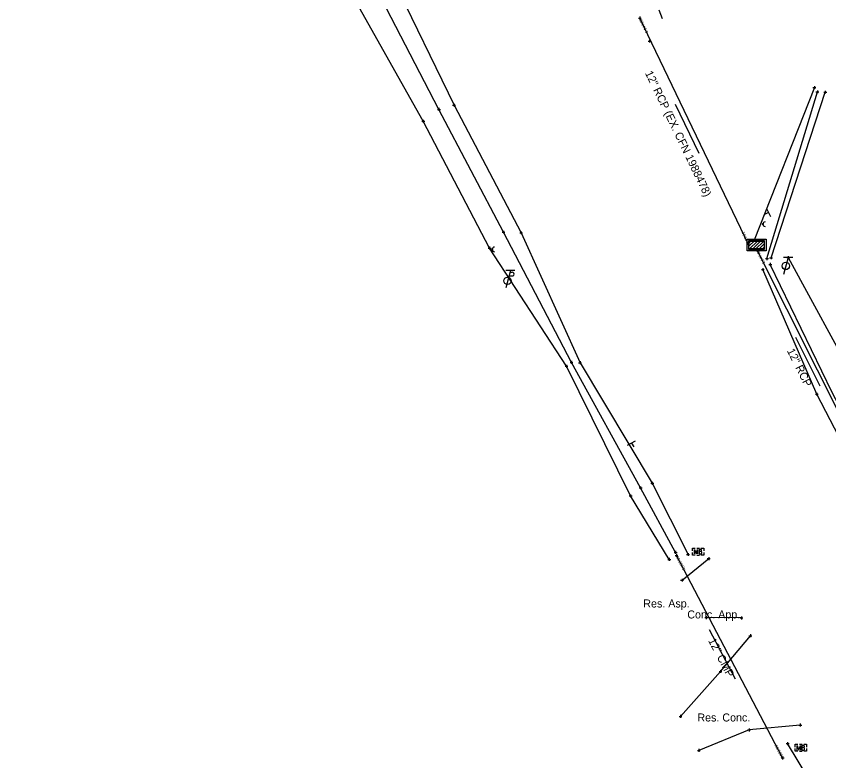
# Model space of a CAD drawing. Extents: x 2298098 to 2302860, y 557788 to 564251.
# Drawn here: x 2298773 to 2299057.3, y 562447.4 to 562708 of the extents above; entities that cross this region are included whole.
import ezdxf

# ---------------------------------------------------------------- set-up
doc = ezdxf.new("R2010")
doc.units = 0
for name, color, linetype in [('DR_X_Cells', 7, 'Continuous'), ('DR_X_Ditch', 7, 'Continuous'), ('DR_X_Elev_Flow', 7, 'Continuous'), ('DR_X_Storm_Sewer', 7, 'Continuous'), ('DR_X_Text', 7, 'Continuous'), ('GK_Drainage_Nodes', 7, 'Continuous'), ('PV_X_Driveway', 7, 'Continuous'), ('PV_X_Text', 7, 'Continuous'), ('RD_X_Cells', 7, 'Continuous'), ('SC_Scratch1', 7, 'Continuous'), ('SN_X_Public', 7, 'Continuous'), ('SV_X_Break_Lines', 7, 'Continuous'), ('SV_X_Shot_Marker', 7, 'Continuous'), ('UT_X_Misc_Cells', 7, 'Continuous'), ('UT_X_Telecom_Cells', 7, 'Continuous')]:
    doc.layers.add(name, color=color, linetype=linetype)

msp = doc.modelspace()

# ---------------------------------------------------------------- linework, layer by layer
at = {"layer": 'DR_X_Cells'}
for p, q in [((2299029.41, 562626.34), (2299032.59, 562629.53)), ((2299029.41, 562627.48), (2299031.46, 562629.53)), ((2299029.41, 562628.61), (2299030.33, 562629.53)), ((2299030.5, 562626.3), (2299033.72, 562629.53)), ((2299031.63, 562626.3), (2299034.74, 562629.41)), ((2299032.76, 562626.3), (2299034.74, 562628.28)), ((2299033.89, 562626.3), (2299034.74, 562627.15))]:
    msp.add_line(p, q, dxfattribs=at)
for points in [[(2299028.74, 562629.91), (2299035.41, 562629.91), (2299035.41, 562625.91), (2299028.74, 562625.91)], [(2299029.41, 562629.53), (2299034.74, 562629.53), (2299034.74, 562626.3), (2299029.41, 562626.3)], [(2299029.41, 562629.25), (2299034.74, 562629.25), (2299034.74, 562626.58), (2299029.41, 562626.58)]]:
    msp.add_lwpolyline(points, close=True, dxfattribs=at)
at = {"layer": 'DR_X_Ditch'}
for points in [[(2299003.75, 562520.37), (2298991.5, 562542.96), (2298967.32, 562586.85), (2298943.53, 562632.42), (2298920.95, 562675.39), (2298897.6, 562720.52), (2298875.32, 562763.99), (2298851.88, 562808.58), (2298829.06, 562850.95), (2298804.9, 562894.79), (2298774.65, 562954.26)], [(2299035.71, 562623.16), (2299053.35, 562681.54)], [(2299086.62, 562522.02), (2299079.1, 562537.23), (2299058.55, 562576.3), (2299036.88, 562621.13)]]:
    msp.add_lwpolyline(points, dxfattribs=at)
at = {"layer": 'DR_X_Elev_Flow'}
for p, q in [((2298990.71, 562707.35), (2298991.71, 562707.35)), ((2298991.21, 562707.85), (2298991.21, 562706.85)), ((2298991.21, 562707.35), (2298991.21, 562707.35)), ((2298994.1, 562699.27), (2298995.1, 562699.27)), ((2298994.6, 562699.77), (2298994.6, 562698.77)), ((2298994.6, 562699.27), (2298994.6, 562699.27)), ((2299003.56, 562519.29), (2299004.56, 562519.29)), ((2299004.06, 562519.79), (2299004.06, 562518.79)), ((2299004.06, 562519.29), (2299004.06, 562519.29)), ((2299040.69, 562448.42), (2299041.69, 562448.42)), ((2299041.19, 562448.92), (2299041.19, 562447.92)), ((2299041.19, 562448.42), (2299041.19, 562448.42))]:
    msp.add_line(p, q, dxfattribs=at)
at = {"layer": 'DR_X_Storm_Sewer'}
for p, q in [((2299029.41, 562627.91), (2298991.21, 562707.35)), ((2299101.62, 562487.9), (2299032.08, 562626.58)), ((2299041.19, 562448.42), (2299004.06, 562519.29))]:
    msp.add_line(p, q, dxfattribs=at)
at = {"layer": 'DR_X_Text'}
for p, q in [((2299003.59, 562677.21), (2299011.87, 562660.01)), ((2299045.71, 562595.69), (2299054.27, 562578.63)), ((2299015.48, 562493.39), (2299024.54, 562476.1))]:
    msp.add_line(p, q, dxfattribs=at)
at = {"layer": 'GK_Drainage_Nodes'}
for p, q in [((2299032.08, 562629.91), (2299032.08, 562629.91)), ((2299029.41, 562627.91), (2299029.41, 562627.91)), ((2299032.08, 562629.25), (2299032.08, 562629.25)), ((2299032.08, 562627.91), (2299032.08, 562627.91)), ((2299032.08, 562627.91), (2299032.08, 562627.91)), ((2299034.74, 562627.91), (2299034.74, 562627.91)), ((2299032.08, 562626.58), (2299032.08, 562626.58)), ((2299032.08, 562626.3), (2299032.08, 562626.3)), ((2299032.08, 562625.91), (2299032.08, 562625.91))]:
    msp.add_line(p, q, dxfattribs=at)
at = {"layer": 'PV_X_Driveway'}
for p, q in [((2299047.39, 562459.92), (2299029.46, 562458.23)), ((2299029.46, 562458.23), (2299011.87, 562451.06))]:
    msp.add_line(p, q, dxfattribs=at)
for points in [[(2299006, 562510.62), (2299015.35, 562518.16)], [(2299026.8, 562497.42), (2299014.48, 562497.53)], [(2299005.44, 562462.97), (2299019.44, 562478.67), (2299029.93, 562491.18)]]:
    msp.add_lwpolyline(points, dxfattribs=at)
at = {"layer": 'RD_X_Cells'}
for p, q in [((2299011.12, 562521.83), (2299012.12, 562521.83)), ((2299011.12, 562519.39), (2299012.12, 562519.39)), ((2299011.63, 562520.61), (2299011.63, 562520.61)), ((2299047.09, 562453.22), (2299048.09, 562453.22)), ((2299047.09, 562450.78), (2299048.09, 562450.78)), ((2299047.6, 562452), (2299047.6, 562452))]:
    msp.add_line(p, q, dxfattribs=at)
for points in [[(2299009.63, 562520.86), (2299009.63, 562521.83), (2299010.6, 562521.83)], [(2299012.63, 562521.83), (2299013.63, 562521.83), (2299013.63, 562520.86)], [(2299010.6, 562519.39), (2299009.63, 562519.39), (2299009.63, 562520.36)], [(2299010.33, 562519.81), (2299010.33, 562521.41), (2299010.91, 562519.81), (2299011.46, 562521.41), (2299011.46, 562519.81)], [(2299012.65, 562520.68), (2299012.71, 562520.74), (2299012.75, 562520.78), (2299012.77, 562520.82), (2299012.79, 562520.84), (2299012.81, 562520.89), (2299012.83, 562520.93), (2299012.85, 562521.02), (2299012.85, 562521.06), (2299012.85, 562521.11), (2299012.84, 562521.18), (2299012.81, 562521.24), (2299012.77, 562521.29), (2299012.71, 562521.34), (2299012.66, 562521.37), (2299012.64, 562521.38), (2299012.57, 562521.41), (2299011.96, 562521.41), (2299011.96, 562519.81), (2299012.65, 562519.81), (2299012.74, 562519.86), (2299012.81, 562519.92), (2299012.88, 562520.02), (2299012.91, 562520.14), (2299012.93, 562520.25), (2299012.93, 562520.32), (2299012.9, 562520.4), (2299012.85, 562520.51), (2299012.79, 562520.59), (2299012.65, 562520.68), (2299011.96, 562520.68)], [(2299013.63, 562520.36), (2299013.63, 562519.39), (2299012.63, 562519.39)], [(2299045.6, 562452.25), (2299045.6, 562453.22), (2299046.57, 562453.22)], [(2299046.57, 562450.78), (2299045.6, 562450.78), (2299045.6, 562451.75)], [(2299046.3, 562451.2), (2299046.3, 562452.8), (2299046.88, 562451.2), (2299047.44, 562452.8), (2299047.44, 562451.2)], [(2299048.62, 562452.07), (2299048.68, 562452.13), (2299048.72, 562452.17), (2299048.75, 562452.21), (2299048.76, 562452.23), (2299048.78, 562452.28), (2299048.8, 562452.32), (2299048.82, 562452.41), (2299048.82, 562452.45), (2299048.82, 562452.5), (2299048.81, 562452.57), (2299048.78, 562452.64), (2299048.75, 562452.69), (2299048.68, 562452.74), (2299048.63, 562452.76), (2299048.61, 562452.78), (2299048.55, 562452.8), (2299047.93, 562452.8), (2299047.93, 562451.2), (2299048.62, 562451.2), (2299048.71, 562451.25), (2299048.78, 562451.31), (2299048.85, 562451.42), (2299048.89, 562451.53), (2299048.9, 562451.64), (2299048.9, 562451.72), (2299048.87, 562451.79), (2299048.82, 562451.91), (2299048.76, 562451.98), (2299048.62, 562452.07), (2299047.93, 562452.07)], [(2299048.61, 562453.22), (2299049.6, 562453.22), (2299049.6, 562452.25)], [(2299049.6, 562451.75), (2299049.6, 562450.78), (2299048.61, 562450.78)]]:
    msp.add_lwpolyline(points, dxfattribs=at)
at = {"layer": 'SN_X_Public'}
for p, q in [((2298997.91, 562710.16), (2298999.07, 562707.18)), ((2299036.25, 562639.33), (2299034.83, 562638.59)), ((2299035.51, 562640.75), (2299036.99, 562637.91)), ((2298986.92, 562557.82), (2298989.69, 562559.44)), ((2298988.31, 562558.63), (2298989.11, 562557.25))]:
    msp.add_line(p, q, dxfattribs=at)
at = {"layer": 'SV_X_Break_Lines'}
for points in [[(2298776.72, 562954.86), (2298790.71, 562942.29), (2298813.67, 562899.02), (2298836.78, 562854.64), (2298857.48, 562808.76), (2298880.71, 562765.1), (2298904.94, 562720.81), (2298926.21, 562676.8), (2298949.69, 562632.19), (2298970.3, 562586.72), (2298995.59, 562544.53), (2299008.11, 562519.62)], [(2299001.55, 562517.92), (2298988, 562540.14), (2298965.59, 562585.47), (2298938.68, 562626.84), (2298915.47, 562671.2), (2298890.85, 562715.15), (2298866.34, 562758.43), (2298846.01, 562803.54), (2298821.84, 562847.56), (2298795.62, 562890.45), (2298777.34, 562936.82), (2298773.04, 562953.6)], [(2299052.32, 562683.06), (2299031.2, 562629.57)], [(2299037.16, 562623.44), (2299056.12, 562681.42)], [(2299043.17, 562623.49), (2299067.28, 562579.23), (2299084.33, 562536.76), (2299089.65, 562521.58)], [(2299081.84, 562521.95), (2299074.99, 562533.75), (2299053.19, 562575.69), (2299034.27, 562619.34)], [(2299303.03, 561961.85), (2299298.64, 561971.05), (2299273.44, 562014.95), (2299250.22, 562059.41), (2299226.48, 562104.95), (2299203.42, 562147.89), (2299181.06, 562192.17), (2299158.67, 562235.79), (2299135.94, 562280.91), (2299112.63, 562324.69), (2299090.03, 562369.28), (2299067.09, 562413.5), (2299042.93, 562453.45)]]:
    msp.add_lwpolyline(points, dxfattribs=at)
at = {"layer": 'SV_X_Shot_Marker'}
for p, q in [((2299051.82, 562683.06), (2299052.82, 562683.06)), ((2299052.32, 562683.56), (2299052.32, 562682.56)), ((2299052.32, 562683.06), (2299052.32, 562683.06)), ((2299052.85, 562681.54), (2299053.85, 562681.54)), ((2299053.35, 562682.04), (2299053.35, 562681.04)), ((2299053.35, 562681.54), (2299053.35, 562681.54)), ((2299055.62, 562681.42), (2299056.62, 562681.42)), ((2299056.12, 562681.92), (2299056.12, 562680.92)), ((2299056.12, 562681.42), (2299056.12, 562681.42)), ((2298920.45, 562675.39), (2298921.45, 562675.39)), ((2298920.95, 562675.89), (2298920.95, 562674.89)), ((2298920.95, 562675.39), (2298920.95, 562675.39)), ((2298925.71, 562676.8), (2298926.71, 562676.8)), ((2298926.21, 562677.3), (2298926.21, 562676.3)), ((2298926.21, 562676.8), (2298926.21, 562676.8)), ((2298914.97, 562671.2), (2298915.97, 562671.2)), ((2298915.47, 562671.7), (2298915.47, 562670.7)), ((2298915.47, 562671.2), (2298915.47, 562671.2)), ((2298943.53, 562632.92), (2298943.53, 562631.92)), ((2298949.69, 562632.69), (2298949.69, 562631.69)), ((2298943.03, 562632.42), (2298944.03, 562632.42)), ((2298943.53, 562632.42), (2298943.53, 562632.42)), ((2298949.19, 562632.19), (2298950.19, 562632.19)), ((2298949.69, 562632.19), (2298949.69, 562632.19)), ((2299031.2, 562630.07), (2299031.2, 562629.07)), ((2298938.68, 562627.34), (2298938.68, 562626.34)), ((2299030.7, 562629.57), (2299031.7, 562629.57)), ((2299031.2, 562629.57), (2299031.2, 562629.57)), ((2298938.18, 562626.84), (2298939.18, 562626.84)), ((2298938.68, 562626.84), (2298938.68, 562626.84)), ((2299035.21, 562623.16), (2299036.21, 562623.16)), ((2299035.71, 562623.66), (2299035.71, 562622.66)), ((2299035.71, 562623.16), (2299035.71, 562623.16)), ((2299036.66, 562623.44), (2299037.66, 562623.44)), ((2299036.88, 562621.63), (2299036.88, 562620.63)), ((2299037.16, 562623.94), (2299037.16, 562622.94)), ((2299037.16, 562623.44), (2299037.16, 562623.44)), ((2299042.67, 562623.49), (2299043.67, 562623.49)), ((2299043.17, 562623.99), (2299043.17, 562622.99)), ((2299043.17, 562623.49), (2299043.17, 562623.49)), ((2299033.77, 562619.34), (2299034.77, 562619.34)), ((2299034.27, 562619.84), (2299034.27, 562618.84)), ((2299034.27, 562619.34), (2299034.27, 562619.34)), ((2299036.38, 562621.13), (2299037.38, 562621.13)), ((2299036.88, 562621.13), (2299036.88, 562621.13)), ((2298967.32, 562587.35), (2298967.32, 562586.35)), ((2298970.3, 562587.22), (2298970.3, 562586.22)), ((2298965.09, 562585.47), (2298966.09, 562585.47)), ((2298965.59, 562585.97), (2298965.59, 562584.97)), ((2298965.59, 562585.47), (2298965.59, 562585.47)), ((2298966.82, 562586.85), (2298967.82, 562586.85)), ((2298967.32, 562586.85), (2298967.32, 562586.85)), ((2298969.8, 562586.72), (2298970.8, 562586.72)), ((2298970.3, 562586.72), (2298970.3, 562586.72)), ((2299052.69, 562575.69), (2299053.69, 562575.69)), ((2299053.19, 562576.19), (2299053.19, 562575.19)), ((2299053.19, 562575.69), (2299053.19, 562575.69)), ((2298995.09, 562544.53), (2298996.09, 562544.53)), ((2298995.59, 562545.03), (2298995.59, 562544.03)), ((2298995.59, 562544.53), (2298995.59, 562544.53)), ((2298991, 562542.96), (2298992, 562542.96)), ((2298991.5, 562543.46), (2298991.5, 562542.46)), ((2298991.5, 562542.96), (2298991.5, 562542.96)), ((2298987.5, 562540.14), (2298988.5, 562540.14)), ((2298988, 562540.64), (2298988, 562539.64)), ((2298988, 562540.14), (2298988, 562540.14)), ((2299003.25, 562520.37), (2299004.25, 562520.37)), ((2299003.75, 562520.87), (2299003.75, 562519.87)), ((2299003.75, 562520.37), (2299003.75, 562520.37)), ((2299007.61, 562519.62), (2299008.61, 562519.62)), ((2299008.11, 562520.12), (2299008.11, 562519.12)), ((2299008.11, 562519.62), (2299008.11, 562519.62)), ((2299001.05, 562517.92), (2299002.05, 562517.92)), ((2299001.55, 562518.42), (2299001.55, 562517.42)), ((2299001.55, 562517.92), (2299001.55, 562517.92)), ((2299014.85, 562518.16), (2299015.85, 562518.16)), ((2299015.35, 562518.66), (2299015.35, 562517.66)), ((2299015.35, 562518.16), (2299015.35, 562518.16)), ((2299005.5, 562510.62), (2299006.5, 562510.62)), ((2299006, 562511.12), (2299006, 562510.12)), ((2299006, 562510.62), (2299006, 562510.62)), ((2299013.98, 562497.53), (2299014.98, 562497.53)), ((2299014.48, 562498.03), (2299014.48, 562497.03)), ((2299014.48, 562497.53), (2299014.48, 562497.53)), ((2299026.3, 562497.42), (2299027.3, 562497.42)), ((2299026.8, 562497.92), (2299026.8, 562496.92)), ((2299026.8, 562497.42), (2299026.8, 562497.42)), ((2299029.43, 562491.18), (2299030.43, 562491.18)), ((2299029.93, 562491.68), (2299029.93, 562490.68)), ((2299029.93, 562491.18), (2299029.93, 562491.18)), ((2299019.44, 562479.17), (2299019.44, 562478.17)), ((2299018.94, 562478.67), (2299019.94, 562478.67)), ((2299019.44, 562478.67), (2299019.44, 562478.67)), ((2299004.94, 562462.97), (2299005.94, 562462.97)), ((2299005.44, 562463.47), (2299005.44, 562462.47)), ((2299005.44, 562462.97), (2299005.44, 562462.97)), ((2299046.89, 562459.92), (2299047.89, 562459.92)), ((2299047.39, 562460.42), (2299047.39, 562459.42)), ((2299047.39, 562459.92), (2299047.39, 562459.92)), ((2299028.96, 562458.23), (2299029.96, 562458.23)), ((2299029.46, 562458.73), (2299029.46, 562457.73)), ((2299029.46, 562458.23), (2299029.46, 562458.23)), ((2299042.43, 562453.45), (2299043.43, 562453.45)), ((2299042.93, 562453.95), (2299042.93, 562452.95)), ((2299042.93, 562453.45), (2299042.93, 562453.45)), ((2299011.37, 562451.06), (2299012.37, 562451.06)), ((2299011.87, 562451.56), (2299011.87, 562450.56)), ((2299011.87, 562451.06), (2299011.87, 562451.06))]:
    msp.add_line(p, q, dxfattribs=at)
at = {"layer": 'UT_X_Misc_Cells'}
for p, q in [((2298945.92, 562618.98), (2298944.31, 562612.98)), ((2298947.52, 562618.98), (2298944.32, 562618.98)), ((2298945.76, 562618.38), (2298946.61, 562618.38)), ((2298945.42, 562617.11), (2298946.61, 562617.11))]:
    msp.add_line(p, q, dxfattribs=at)
for centre, radius in [((2299034.27, 562635.23), 0.2), ((2298939.56, 562626.37), 0.2), ((2298944.95, 562615.38), 1.3)]:
    msp.add_circle(centre, radius, dxfattribs=at)
for centre, radius, start, end in [((2299035.07, 562635.23), 0.8, 90, 270), ((2298940.36, 562626.37), 0.8, 90, 270), ((2298946.62, 562617.74), 0.638, 268.8767, 91.1233)]:
    msp.add_arc(centre, radius, start, end, dxfattribs=at)
at = {"layer": 'UT_X_Telecom_Cells'}
for p, q in [((2299043.12, 562623.6), (2299041.51, 562617.6)), ((2299044.72, 562623.6), (2299041.52, 562623.6))]:
    msp.add_line(p, q, dxfattribs=at)
msp.add_circle((2299042.31, 562620.6), 1.3, dxfattribs=at)

# ---------------------------------------------------------------- texts
at = {"layer": 'DR_X_Text'}
for s, rotation, p in [('12" RCP (EX. CFN 1988478)', 295.6821, (2298992.97, 562688.1)), ('12" RCP', 296.6334, (2299042.62, 562590.89)), ('12" CMP', 297.6486, (2299015.04, 562489.49))]:
    msp.add_text(s, height=2.8, rotation=rotation, dxfattribs=at).set_placement(p)
at = {"layer": 'PV_X_Text'}
for s, p in [('Res. Asp.', (2298992.44, 562501.07)), ('Conc. App.', (2299007.84, 562497.23)), ('Res. Conc.', (2299011.36, 562461.18))]:
    msp.add_text(s, height=2.8, dxfattribs=at).set_placement(p)
at = {"layer": 'SC_Scratch1'}
for s, rotation, p in [("1,147.25'", 115.6821, (2298994.17, 562702.35)), ("1147.81'", 115.6821, (2299029.86, 562628.13)), ("1,147.81'", 116.6334, (2299035.12, 562621.62)), ("1,147.81'", 116.6334, (2299035.12, 562621.62)), ("1,150.19'", 117.6486, (2299007.19, 562514.39)), ("1150.86'", 117.6486, (2299041.63, 562448.65))]:
    msp.add_text(s, height=1, rotation=rotation, dxfattribs=at).set_placement(p)

doc.saveas('drawing.dxf')
